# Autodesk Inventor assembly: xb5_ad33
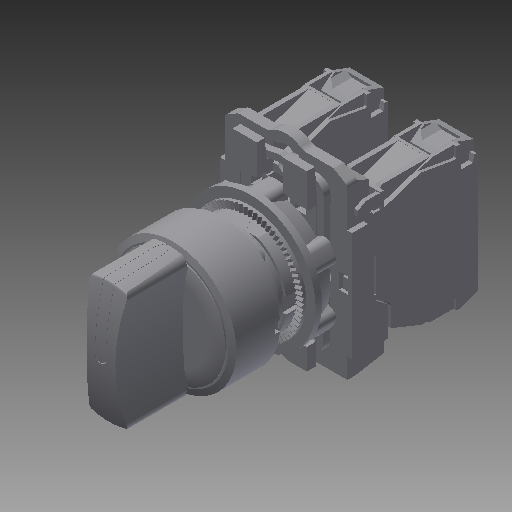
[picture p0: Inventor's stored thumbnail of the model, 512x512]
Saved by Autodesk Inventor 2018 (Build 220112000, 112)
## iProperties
Company: TraceParts S.A.
Created: 2018-05
Part Number: xb5_ad33
Checked By: TraceParts S.A.
Catalog Web Link: www.traceparts.com
Document SubType Name: Assembly
Designer: TraceParts
REFERENCE: XB5 AD33
DESIGN: Control and signalling units Ø 22, Harmony® XB5 plastic, Selector switch with standard handle, Complete units, 3 position stay put, Type of contact 2 "F", Black
SUPPLIER: Schneider Electric
TraceParts.PartNumber: 10-14022008-080708
TraceParts.PartTitle: Control and signalling units Ø 22, Harmony® XB5 plastic, Selector switch with standard handle, Complete units
TraceParts.InstanceId: 10-14022008-080708CDPOYEWXPS4XMJOUSCCWBS2PD
TraceParts.PartStatus: Published
TraceParts.PartVersion: 1.2.3
TRACEPARTS: TRACEPARTS
TraceParts.PartLanguage: en
TraceParts.ClassPath: SCHNEIDER_ELECTRIC:/F_SCHNEIDER/F_TELEMECANIQUE/F_TELEMECANIQUE.04/F_TELEMECANIQUE.04.010/F_TELEMECANIQUE.04.010.020/10-14022008-080708
Author: TraceParts
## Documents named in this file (7)
- D:\01 Paralaia\Grupos de Traballo\GT Maquetas\CAD 3D\Botoneras Schneider\Selector XB5AD33\xb5_ad33.iam
- D:\01 Paralaia\Grupos de Traballo\GT Maquetas\CAD 3D\Botoneras Schneider\Selector XB5AD33\xb5_ad33_01.ipt
- D:\01 Paralaia\Grupos de Traballo\GT Maquetas\CAD 3D\Botoneras Schneider\Selector XB5AD33\xb5_ad33_02.ipt
- D:\01 Paralaia\Grupos de Traballo\GT Maquetas\CAD 3D\Botoneras Schneider\Selector XB5AD33\xb5_ad33_03.ipt
- D:\01 Paralaia\Grupos de Traballo\GT Maquetas\CAD 3D\Botoneras Schneider\Selector XB5AD33\xb5_ad33_04.ipt
- D:\01 Paralaia\Grupos de Traballo\GT Maquetas\CAD 3D\Botoneras Schneider\Selector XB5AD33\xb5_ad33_05.ipt
- D:\01 Paralaia\Grupos de Traballo\GT Maquetas\CAD 3D\Botoneras Schneider\Selector XB5AD33\xb5_ad33_06.ipt
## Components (6 placed, 6 different names)
1. xb5_ad33_01:1
2. xb5_ad33_02:1
3. xb5_ad33_03:1
4. xb5_ad33_04:1
5. xb5_ad33_05:1
6. xb5_ad33_06:1
